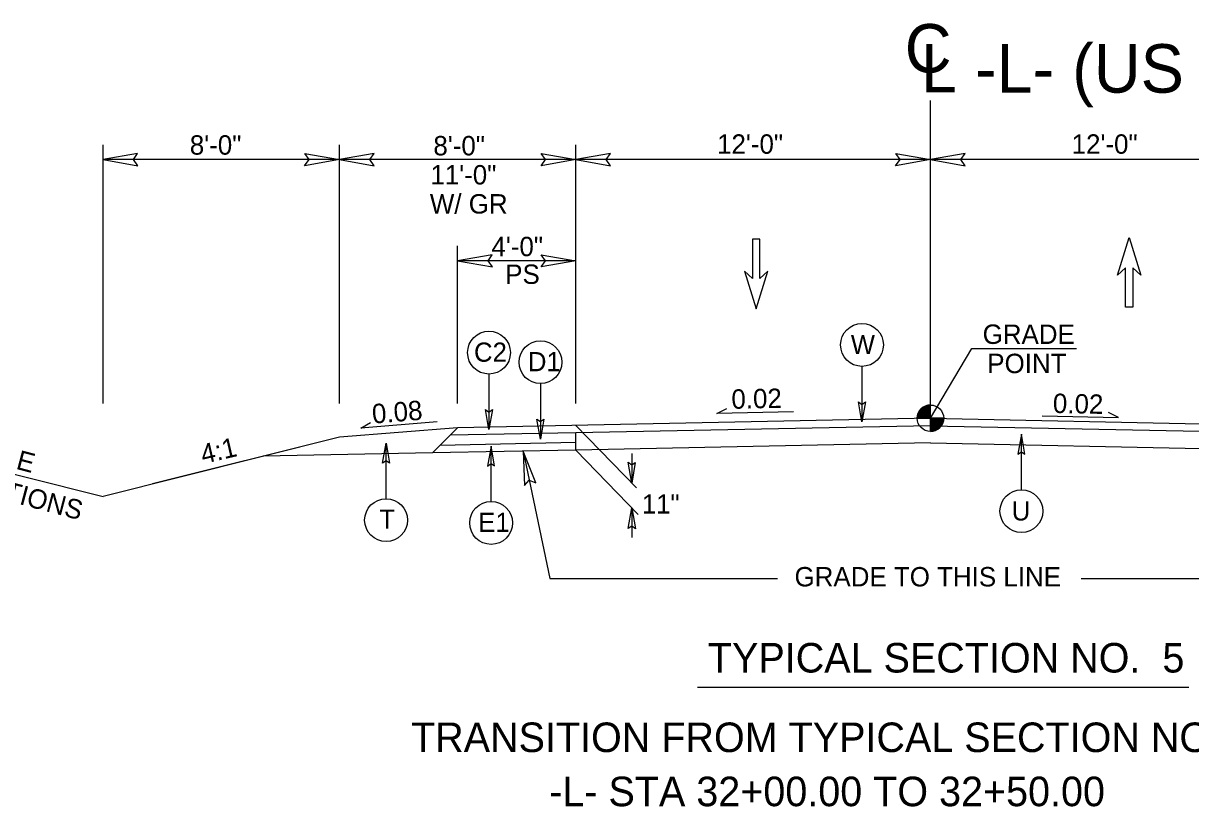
# Model space of a CAD drawing. Extents: x 1901582 to 1902252, y 193723 to 194156.
# Drawn here: x 1902015.93 to 1902055.44, y 193944.15 to 193970.65 of the extents above; entities that cross this region are included whole.
import ezdxf

# ---------------------------------------------------------------- set-up
doc = ezdxf.new("R2010")
doc.units = 0
for name, color, linetype in [('Old_Level_1', 7, 'Continuous'), ('Old_Level_11', 7, 'Continuous'), ('Old_Level_2', 7, 'Continuous'), ('Old_Level_20', 7, 'Continuous'), ('Prop Dimension', 7, 'Continuous'), ('Prop Dimension Text', 7, 'Continuous'), ('Typical Grade Point Symbol CELL', 7, 'Continuous'), ('Typical Pavement Slope Information CELL', 7, 'Continuous'), ('Typical Slope Point Local CELL', 7, 'Continuous'), ('Typical Terminator CELL', 7, 'Continuous'), ('Typical Text Centerline CELL', 7, 'Continuous'), ('Typical Text Grade Point CELL', 7, 'Continuous')]:
    doc.layers.add(name, color=color, linetype=linetype)

# ---------------------------------------------------------------- blocks, each defined once
blk = doc.blocks.new('TERMINATOR')
at = {"layer": 'Typical Terminator CELL'}
blk.add_lwpolyline([(-0.469, 0.081), (0, 0), (-0.471, -0.083), (-0.411, 0)], close=True, dxfattribs=at)

msp = doc.modelspace()

# ---------------------------------------------------------------- linework, layer by layer
at = {"layer": 'Old_Level_1'}
for p, q in [((1902018.631, 193957.787), (1902018.631, 193966.537)), ((1902026.631, 193957.787), (1902026.631, 193966.537)), ((1902034.631, 193957.787), (1902034.631, 193966.537)), ((1902026.631, 193966.037), (1902018.631, 193966.037)), ((1902034.631, 193966.037), (1902026.631, 193966.037)), ((1902046.631, 193966.037), (1902034.631, 193966.037)), ((1902058.631, 193966.037), (1902046.631, 193966.037)), ((1902030.631, 193957.787), (1902030.631, 193963.118)), ((1902034.631, 193962.618), (1902030.631, 193962.618)), ((1902046.631, 193957.287), (1902030.631, 193956.967)), ((1902034.631, 193957.047), (1902036.68, 193954.931)), ((1902046.636, 193957.037), (1902034.631, 193956.797)), ((1902046.631, 193957.287), (1902062.631, 193956.967)), ((1902046.631, 193957.037), (1902058.631, 193956.797)), ((1902026.631, 193956.647), (1902020.31, 193955.066)), ((1902030.631, 193956.967), (1902026.631, 193956.647)), ((1902029.781, 193956.116), (1902030.631, 193956.967)), ((1902034.631, 193956.797), (1902030.376, 193956.712)), ((1902034.631, 193956.213), (1902034.631, 193956.797)), ((1902034.631, 193956.213), (1902029.781, 193956.116)), ((1902034.631, 193956.463), (1902030.036, 193956.372)), ((1902046.631, 193956.453), (1902034.631, 193956.213)), ((1902034.631, 193956.213), (1902036.738, 193954.037)), ((1902046.631, 193956.453), (1902058.631, 193956.213)), ((1902029.781, 193956.116), (1902024.051, 193956.002)), ((1902032.853, 193956.178), (1902033.755, 193951.867)), ((1902036.522, 193956.093), (1902036.522, 193955.093)), ((1902036.522, 193954.26), (1902036.522, 193953.26)), ((1902033.755, 193951.867), (1902041.453, 193951.867)), ((1902051.735, 193951.867), (1902059.508, 193951.867))]:
    msp.add_line(p, q, dxfattribs=at)
for points in [[(1902010.631, 193956.647), (1902018.631, 193954.647)], [(1902026.631, 193956.647), (1902018.631, 193954.647)]]:
    msp.add_lwpolyline(points, dxfattribs=at)
at = {"layer": 'Old_Level_11'}
for p, q in [((1902046.631, 193957.287), (1902046.631, 193968.037)), ((1902044.316, 193959.042), (1902044.316, 193957.168)), ((1902031.693, 193958.781), (1902031.693, 193956.907)), ((1902033.434, 193958.46), (1902033.434, 193956.586)), ((1902049.711, 193954.871), (1902049.711, 193956.745)), ((1902028.21, 193954.568), (1902028.21, 193956.442)), ((1902031.765, 193954.473), (1902031.765, 193956.347)), ((1902038.745, 193948.194), (1902055.371, 193948.194))]:
    msp.add_line(p, q, dxfattribs=at)
for points in [[(1902044.431, 193957.839), (1902044.316, 193957.168), (1902044.196, 193957.843), (1902044.316, 193957.757)], [(1902031.809, 193957.579), (1902031.693, 193956.907), (1902031.574, 193957.582), (1902031.693, 193957.497)], [(1902033.549, 193957.257), (1902033.434, 193956.586), (1902033.314, 193957.261), (1902033.434, 193957.175)], [(1902049.827, 193956.074), (1902049.711, 193956.745), (1902049.592, 193956.07), (1902049.711, 193956.156)], [(1902028.094, 193955.77), (1902028.21, 193956.442), (1902028.329, 193955.767), (1902028.21, 193955.852)], [(1902031.88, 193955.676), (1902031.765, 193956.347), (1902031.645, 193955.672), (1902031.765, 193955.758)]]:
    msp.add_lwpolyline(points, close=True, dxfattribs=at)
for centre in [(1902031.693, 193959.507), (1902044.316, 193959.767), (1902033.434, 193959.185), (1902049.711, 193954.146), (1902028.21, 193953.843), (1902031.764, 193953.748)]:
    msp.add_circle(centre, 0.725, dxfattribs=at)
at = {"layer": 'Prop Dimension'}
for points in [[(1902041.128, 193962.26), (1902040.857, 193962.01), (1902040.857, 193963.343), (1902040.607, 193963.343), (1902040.607, 193962.01), (1902040.337, 193962.26), (1902040.732, 193960.989)], [(1902041.128, 193962.26), (1902040.857, 193962.01), (1902040.857, 193963.343), (1902040.607, 193963.343), (1902040.607, 193962.01), (1902040.337, 193962.26), (1902040.732, 193960.989)], [(1902053.751, 193962.129), (1902053.481, 193962.379), (1902053.481, 193961.045), (1902053.231, 193961.045), (1902053.231, 193962.379), (1902052.96, 193962.129), (1902053.356, 193963.399)], [(1902053.751, 193962.129), (1902053.481, 193962.379), (1902053.481, 193961.045), (1902053.231, 193961.045), (1902053.231, 193962.379), (1902052.96, 193962.129), (1902053.356, 193963.399)]]:
    msp.add_lwpolyline(points, close=True, dxfattribs=at)
at = {"layer": 'Typical Grade Point Symbol CELL'}
for p, q in [((1902046.631, 193957.287), (1902046.631, 193957.734)), ((1902046.184, 193957.287), (1902046.631, 193957.287)), ((1902046.632, 193956.839), (1902046.631, 193957.287)), ((1902047.079, 193957.287), (1902046.631, 193957.287)), ((1902046.631, 193957.287), (1902046.632, 193956.839))]:
    msp.add_line(p, q, dxfattribs=at)
for points in [[(1902046.198, 193957.396), (1902046.198, 193957.287)], [(1902046.207, 193957.427), (1902046.207, 193957.287)], [(1902046.216, 193957.452), (1902046.216, 193957.287)], [(1902046.224, 193957.473), (1902046.224, 193957.287)], [(1902046.233, 193957.492), (1902046.233, 193957.287)], [(1902046.242, 193957.508), (1902046.242, 193957.287)], [(1902046.251, 193957.523), (1902046.251, 193957.287)], [(1902046.26, 193957.537), (1902046.26, 193957.287)], [(1902046.269, 193957.55), (1902046.269, 193957.287)], [(1902046.278, 193957.561), (1902046.278, 193957.287)], [(1902046.287, 193957.572), (1902046.287, 193957.287)], [(1902046.296, 193957.583), (1902046.296, 193957.287)], [(1902046.305, 193957.593), (1902046.305, 193957.287)], [(1902046.314, 193957.602), (1902046.314, 193957.287)], [(1902046.323, 193957.611), (1902046.323, 193957.287)], [(1902046.332, 193957.619), (1902046.332, 193957.287)], [(1902046.341, 193957.627), (1902046.341, 193957.287)], [(1902046.35, 193957.635), (1902046.35, 193957.287)], [(1902046.359, 193957.642), (1902046.359, 193957.287)], [(1902046.368, 193957.648), (1902046.368, 193957.287)], [(1902046.377, 193957.655), (1902046.377, 193957.287)], [(1902046.386, 193957.661), (1902046.386, 193957.287)], [(1902046.395, 193957.667), (1902046.395, 193957.287)], [(1902046.404, 193957.672), (1902046.404, 193957.287)], [(1902046.412, 193957.677), (1902046.412, 193957.287)], [(1902046.421, 193957.682), (1902046.421, 193957.287)], [(1902046.43, 193957.687), (1902046.43, 193957.287)], [(1902046.439, 193957.691), (1902046.439, 193957.287)], [(1902046.448, 193957.695), (1902046.448, 193957.287)], [(1902046.457, 193957.699), (1902046.457, 193957.287)], [(1902046.466, 193957.703), (1902046.466, 193957.287)], [(1902046.475, 193957.707), (1902046.475, 193957.287)], [(1902046.484, 193957.71), (1902046.484, 193957.287)], [(1902046.493, 193957.713), (1902046.493, 193957.287)], [(1902046.502, 193957.716), (1902046.502, 193957.287)], [(1902046.511, 193957.718), (1902046.511, 193957.287)], [(1902046.52, 193957.721), (1902046.52, 193957.287)], [(1902046.529, 193957.723), (1902046.529, 193957.287)], [(1902046.538, 193957.725), (1902046.538, 193957.287)], [(1902046.547, 193957.727), (1902046.547, 193957.287)], [(1902046.556, 193957.729), (1902046.556, 193957.287)], [(1902046.565, 193957.73), (1902046.565, 193957.287)], [(1902046.574, 193957.731), (1902046.574, 193957.287)], [(1902046.583, 193957.732), (1902046.583, 193957.287)], [(1902046.592, 193957.732), (1902046.592, 193957.287)], [(1902046.6, 193957.733), (1902046.6, 193957.287)], [(1902046.609, 193957.733), (1902046.609, 193957.287)], [(1902046.618, 193957.734), (1902046.618, 193957.287)], [(1902046.627, 193957.734), (1902046.627, 193957.734), (1902046.627, 193957.287)], [(1902046.189, 193957.351), (1902046.189, 193957.287)], [(1902046.638, 193957.287), (1902046.638, 193956.839), (1902046.638, 193956.839)], [(1902046.647, 193957.287), (1902046.647, 193956.839)], [(1902046.656, 193957.287), (1902046.656, 193956.84)], [(1902046.665, 193957.287), (1902046.665, 193956.84)], [(1902046.674, 193957.287), (1902046.674, 193956.841)], [(1902046.683, 193957.287), (1902046.683, 193956.842)], [(1902046.692, 193957.287), (1902046.692, 193956.843)], [(1902046.701, 193957.287), (1902046.701, 193956.845)], [(1902046.71, 193957.287), (1902046.71, 193956.846)], [(1902046.719, 193957.287), (1902046.719, 193956.848)], [(1902046.728, 193957.287), (1902046.728, 193956.85)], [(1902046.737, 193957.287), (1902046.737, 193956.852)], [(1902046.746, 193957.287), (1902046.746, 193956.854)], [(1902046.755, 193957.287), (1902046.755, 193956.857)], [(1902046.764, 193957.287), (1902046.764, 193956.859)], [(1902046.773, 193957.287), (1902046.773, 193956.862)], [(1902046.781, 193957.287), (1902046.781, 193956.865)], [(1902046.79, 193957.287), (1902046.79, 193956.868)], [(1902046.799, 193957.287), (1902046.799, 193956.872)], [(1902046.808, 193957.287), (1902046.808, 193956.876)], [(1902046.817, 193957.287), (1902046.817, 193956.88)], [(1902046.826, 193957.287), (1902046.826, 193956.884)], [(1902046.835, 193957.287), (1902046.835, 193956.888)], [(1902046.844, 193957.287), (1902046.844, 193956.893)], [(1902046.853, 193957.287), (1902046.853, 193956.898)], [(1902046.862, 193957.287), (1902046.862, 193956.903)], [(1902046.871, 193957.287), (1902046.871, 193956.909)], [(1902046.88, 193957.287), (1902046.88, 193956.915)], [(1902046.889, 193957.287), (1902046.889, 193956.921)], [(1902046.898, 193957.287), (1902046.898, 193956.927)], [(1902046.907, 193957.287), (1902046.907, 193956.934)], [(1902046.916, 193957.287), (1902046.916, 193956.941)], [(1902046.925, 193957.287), (1902046.925, 193956.949)], [(1902046.934, 193957.287), (1902046.934, 193956.957)], [(1902046.943, 193957.287), (1902046.943, 193956.965)], [(1902046.952, 193957.287), (1902046.952, 193956.974)], [(1902046.961, 193957.287), (1902046.961, 193956.984)], [(1902046.969, 193957.287), (1902046.969, 193956.993)], [(1902046.978, 193957.287), (1902046.978, 193957.004)], [(1902046.987, 193957.287), (1902046.987, 193957.015)], [(1902046.996, 193957.287), (1902046.996, 193957.027)], [(1902047.005, 193957.287), (1902047.005, 193957.04)], [(1902047.014, 193957.287), (1902047.014, 193957.054)], [(1902047.023, 193957.287), (1902047.023, 193957.07)], [(1902047.032, 193957.287), (1902047.032, 193957.087)], [(1902047.041, 193957.287), (1902047.041, 193957.106)], [(1902047.05, 193957.287), (1902047.05, 193957.127)], [(1902047.059, 193957.287), (1902047.059, 193957.154)], [(1902047.068, 193957.287), (1902047.068, 193957.185)], [(1902047.077, 193957.287), (1902047.077, 193957.238)]]:
    msp.add_lwpolyline(points, dxfattribs=at)
msp.add_circle((1902046.632, 193957.287), 0.448, dxfattribs=at)
for start, end in [(90.0095, 180.0095), (270.0095, 0.0095)]:
    msp.add_arc((1902046.632, 193957.287), 0.448, start, end, dxfattribs=at)
at = {"layer": 'Typical Pavement Slope Information CELL'}
for p, q in [((1902039.409, 193957.446), (1902039.742, 193957.614)), ((1902041.997, 193957.509), (1902039.409, 193957.446)), ((1902050.408, 193957.373), (1902052.996, 193957.318)), ((1902052.996, 193957.318), (1902052.663, 193957.485)), ((1902029.941, 193957.163), (1902027.361, 193956.956)), ((1902027.361, 193956.956), (1902027.684, 193957.143))]:
    msp.add_line(p, q, dxfattribs=at)
at = {"layer": 'Typical Terminator CELL'}
for points in [[(1902019.803, 193966.239), (1902018.631, 193966.037), (1902019.809, 193965.829), (1902019.66, 193966.037)], [(1902025.46, 193966.239), (1902026.631, 193966.037), (1902025.453, 193965.829), (1902025.603, 193966.037)], [(1902027.803, 193966.239), (1902026.631, 193966.037), (1902027.809, 193965.829), (1902027.66, 193966.037)], [(1902033.46, 193966.239), (1902034.631, 193966.037), (1902033.453, 193965.829), (1902033.603, 193966.037)], [(1902035.803, 193966.239), (1902034.631, 193966.037), (1902035.809, 193965.829), (1902035.66, 193966.037)], [(1902045.46, 193966.239), (1902046.631, 193966.037), (1902045.453, 193965.829), (1902045.603, 193966.037)], [(1902047.803, 193966.239), (1902046.631, 193966.037), (1902047.809, 193965.829), (1902047.66, 193966.037)], [(1902031.803, 193962.82), (1902030.631, 193962.618), (1902031.809, 193962.41), (1902031.66, 193962.618)], [(1902033.46, 193962.82), (1902034.631, 193962.618), (1902033.453, 193962.41), (1902033.603, 193962.618)], [(1902033.279, 193955.102), (1902032.853, 193956.178), (1902032.889, 193955.014), (1902033.058, 193955.199)]]:
    msp.add_lwpolyline(points, close=True, dxfattribs=at)
at = {"layer": 'Typical Text Grade Point CELL'}
for p, q in [((1902046.631, 193957.287), (1902048.035, 193959.647)), ((1902048.035, 193959.647), (1902051.573, 193959.647))]:
    msp.add_line(p, q, dxfattribs=at)

# ---------------------------------------------------------------- block references
at = {"layer": 'Old_Level_1', "xscale": 1.5, "yscale": 1.5}
for p, rotation in [((1902036.522, 193955.093), -90), ((1902036.522, 193954.26), 90)]:
    msp.add_blockref('TERMINATOR', p, dxfattribs=dict(at, rotation=rotation))

# ---------------------------------------------------------------- texts
at = {"layer": 'Old_Level_1'}
for s, p in [('12\'-0"', (1902039.411, 193966.235)), ('12\'-0"', (1902051.411, 193966.235)), ('8\'-0"', (1902029.811, 193966.18)), ('11\'-0"', (1902029.709, 193965.196)), ('W/ GR', (1902029.692, 193964.212)), ('4\'-0"', (1902031.776, 193962.77)), ('GRADE TO THIS LINE', (1902042.033, 193951.6))]:
    msp.add_text(s, height=0.656, dxfattribs=at).set_placement(p)
for s, rotation, p in [('VARIABLE', 345.2456, (1902012.074, 193956.526)), ('SEE X-SECTIONS', 345.1369, (1902010.728, 193955.726))]:
    msp.add_text(s, height=0.656, rotation=rotation, dxfattribs=at).set_placement(p)
at = {"layer": 'Old_Level_11'}
for s, p in [('TYPICAL SECTION NO.  5', (1902039.101, 193948.688)), ('TRANSITION FROM TYPICAL SECTION NO. 5 TO EXISTING: ', (1902029.055, 193945.997)), ('-L- STA 32+00.00 TO 32+50.00', (1902033.731, 193944.166))]:
    msp.add_text(s, height=1, dxfattribs=at).set_placement(p)
at = {"layer": 'Old_Level_2'}
for s, rotation, p in [('0.02', 1.1916, (1902039.903, 193957.606)), ('0.08', 4.5739, (1902027.761, 193957.106)), ('0.02', 358.8084, (1902050.77, 193957.469))]:
    msp.add_text(s, height=0.656, rotation=rotation, dxfattribs=at).set_placement(p)
at = {"layer": 'Old_Level_20'}
for s, height, p in [('C2', 0.6491, (1902031.187, 193959.2)), ('W', 0.649, (1902043.937, 193959.461)), ('D1', 0.6491, (1902033.011, 193958.879)), ('11"', 0.6491, (1902036.869, 193954.065)), ('U', 0.649, (1902049.383, 193953.831)), ('T', 0.649, (1902027.982, 193953.549)), ('E1', 0.6491, (1902031.331, 193953.444))]:
    msp.add_text(s, height=height, dxfattribs=at).set_placement(p)
at = {"layer": 'Prop Dimension Text'}
for s, p in [('8\'-0"', (1902021.568, 193966.204)), ('PS', (1902032.242, 193961.833))]:
    msp.add_text(s, height=0.656, dxfattribs=at).set_placement(p)
at = {"layer": 'Typical Slope Point Local CELL'}
msp.add_text('4:1', height=0.656, rotation=13.0197, dxfattribs=at).set_placement((1902022.02, 193955.739))
at = {"layer": 'Typical Text Centerline CELL'}
msp.add_text('C', height=1.64, dxfattribs=at).set_placement((1902045.763, 193968.981))
msp.add_text('L -L- (US 29 BUS)', height=1.64109, rotation=359.9469, dxfattribs=at).set_placement((1902046.308, 193968.308))
at = {"layer": 'Typical Text Grade Point CELL'}
for s, p in [('GRADE', (1902048.399, 193959.803)), ('POINT', (1902048.556, 193958.815))]:
    msp.add_text(s, height=0.656, dxfattribs=at).set_placement(p)

doc.saveas('drawing.dxf')
